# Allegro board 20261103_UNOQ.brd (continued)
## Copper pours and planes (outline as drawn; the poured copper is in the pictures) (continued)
PWR_3P3V on V5: 14.3,7.82 15.24,7.82 15.96,8.54 15.96,11.29 18.24,13.57 20.97,13.57 21.64,12.9 21.64,11.38 22.76,10.26 31.96,10.26 32.58,10.88 32.58,11.64 32.42,11.8 25.18,11.8 21.46,15.52 17.57,15.52 14.51,18.58 14.51,20.65 14.37,20.79 12.71,20.79 12.71,17.95 15.51,15.15 15.51,13.48 14.17,12.14 14.17,7.95
PWR_3P3V on S6: 12.8,30.23 13.34,30.23 13.51,30.05 13.51,27.89 13.26,27.64 12.83,27.64 12.67,27.79 12.67,30.1
PWR_3P3V on G7: 6.48,59.02 6.48,50 7.19,49.29 7.19,47.44 6.81,47.05 6.81,46.14 7.19,45.76 7.19,38.32 4.63,35.76 4.63,32.75 4.06,32.18 1.08,32.18 0.9,32.36 0.9,41.33 4.18,44.61 4.18,60.44 5.6,61.86 9.83,61.86 10.13,61.56 10.13,59.97 9.95,59.79 7.25,59.79
PWR_3P8V on BOTTOM (solid shape): 10.11,46.2 10.11,42.7 9.17,42.7 8.69,42.21 6.88,42.21 6.76,42.34 6.76,43.54 7.75,44.53 7.75,46.18 7.95,46.38 9.93,46.38
PWR_3P8V on V5: 15.47,42.6 15.67,42.39 15.67,42.15 14.72,41.2 13.94,41.2 13.51,40.77 13.51,37.01 13.21,36.7 12.29,36.7 11.86,37.13 11.86,38.2 11.87,38.21 11.87,41.54 11.87,41.54 11.87,42.31 12.16,42.6
PWR_3P8V on S6: 15.63,42.59 15.22,42.59 14.64,42.01 11.42,42.01 10.33,43.1 10.33,43.32 10.14,43.51 9.86,43.51 9.78,43.43 9.78,42.85 11.18,41.45 14.75,41.45 15.67,42.37 15.67,42.55
PWR_3P8V on S6: 10.86,35.15 9.52,33.8 9.52,31.7 9.57,31.64 9.96,31.64 13.01,34.68 13.01,36.28 13.47,36.76 13.47,37.14 13.47,37.14 13.47,37.71 13.38,37.8 11.8,37.8 10.86,36.85
USB_IN_MID on TOP: 40.97,11.76 40.97,12.21 40.65,12.53 40.65,13.13 40.75,13.23 40.87,13.23 41.7,12.4 41.7,11.73 41,11.73
USB_VBUS_IN on TOP: 39.9,9.93 39.9,12.9 40.15,13.15 40.36,13.15 40.55,12.96 40.55,12.53 40.34,12.32 40.34,10.74 40.56,10.52 40.56,9.88 40.54,9.86 39.98,9.86
VCOIN on BOTTOM (solid shape): 8.61,8.94 8.61,7.04 8.38,6.81 6.48,6.81 6.32,6.96 6.32,8.61 6.76,9.04 8.51,9.04
VCONN_IN on TOP (solid shape): 32.31,50.95 32.41,50.85 32.82,50.85 32.87,50.8 32.87,50.39 32.94,50.32 33.38,50.32 33.43,50.27 33.43,50.01 31.72,50.01 31.7,50.04 31.7,51.44 32.31,51.44
VPH_PWR on TOP: 34.81,18.34 34.29,18.34 32.92,19.71 32.36,19.71 32.36,19.15 32.38,19.13 32.87,19.13 33.87,18.13 34.88,18.13 34.88,18.28
VPH_PWR on TOP: 46.56,10.85 46.56,13.84 46.41,14 45.74,14 44.78,14.96 41.92,14.96 41.64,14.68 41.43,14.68 40.89,15.22 40.72,15.22 40.59,15.09 40.59,15.01 41.27,14.33 41.51,14.33 41.78,14.06 43.93,14.06 44.65,13.34 44.65,10.87 44.83,10.69 46.41,10.69
VPH_PWR on S3: 45.82,14.02 45.82,11.61 46.51,11.61 46.51,14.02
VPH_PWR on S6: 46.48,13.94 46.48,11.63 45.77,11.63 45.77,13.94
VPH_PWR on G7: 32.18,17.07 32.18,19.05 32.69,19.56 36.81,19.56 37.8,20.55 39.65,20.55 41.27,18.93 41.27,15.23 40.8,14.76 40.8,13.79 41.08,13.51 45.19,13.51 45.72,14.05 46.15,14.05 46.87,13.33 46.87,11.89 46.32,11.34 37.94,11.34 37.76,11.52 37.76,13.7 38.31,14.25 39.01,14.25 39.22,14.46 39.22,15.44 38.68,15.98 38.68,18.21 38.33,18.57 36.8,18.57 36.27,18.03 36.27,17.37 36.78,16.87 36.78,15.72 36.55,15.49 36.55,15.14 35.84,15.14 35.71,15.27 35.71,16.05 35.31,16.46 32.79,16.46
VREG_L1A_0P848V on TOP: 36.34,17.93 36.34,18.61 35.94,19.01 36.03,19.01 36.03,19.01 35.3,19.01 34.87,19.44 34.87,21.56 35.48,21.56 35.48,19.99 35.93,19.54 36.21,19.54 36.88,18.87 36.88,17.86 36.85,17.83 36.43,17.83
VREG_L1A_0P848V on BOTTOM: 28.21,37.21 28.21,35.45 28.4,35.26 28.4,34.37 28.91,34.37 28.91,35.26 28.72,35.45 28.72,37.27 28.95,37.5 28.95,37.75 28.9,37.8 28.55,37.8 28.5,37.75 28.5,37.49
VREG_L1A_0P848V on BOTTOM: 30.98,35.8 31.3,35.8 31.3,35.42 31.27,35.38 31.17,35.38 31.14,35.35 31.14,32.78 31.65,32.78 31.68,32.81 31.68,33.09 31.65,33.13 31.49,33.13 31.46,33.16 31.46,34.24 31.52,34.3 31.87,34.3 31.9,34.34 31.9,34.62 31.82,34.7 31.6,34.7 31.55,34.75 31.55,36.1 31.3,36.35 31.3,36.75 31.25,36.8 30.96,36.8 30.92,36.75 30.92,35.86
VREG_L1A_0P848V on BOTTOM: 32.44,35.7 32.44,35.35 32.49,35.31 32.49,34.19 32.54,34.14 32.54,33.09 32.44,33 32.44,31.65 32.75,31.65 32.75,31.8 32.82,31.87 32.82,32.59 32.89,32.65 33.21,32.65 33.21,32.94 33.17,32.97 32.97,32.97 32.79,33.15 32.79,34.21 32.73,34.27 32.67,34.27 32.63,34.3 32.63,34.65 32.67,34.69 32.89,34.69 33,34.8 33,36.5 32.7,36.5 32.7,35.96
VREG_L1A_0P848V on G2: 31.2,36.56 31.2,32.65 31.17,32.62 30.18,32.62 29.8,33 29.71,33 29.64,32.94 29.64,32.81 30.22,32.24 31.49,32.24 31.55,32.3 31.55,36.53 31.46,36.62 31.27,36.62
VREG_L1A_0P848V on G2: 28.4,36.91 28.4,35.29 28.31,35.19 27.99,35.19 27.9,35.1 27.77,35.1 27.67,35 27.67,34.43 27.74,34.37 28.21,34.37 28.28,34.43 28.28,34.53 28.21,34.59 28.05,34.59 27.99,34.65 27.99,34.97 28.05,35.03 28.4,35.03 28.44,35 28.44,34.81 28.47,34.78 28.69,34.78 28.75,34.84 28.75,36.91 28.66,37.01 28.5,37.01
VREG_L1A_0P848V on S3: 30.69,32.17 31.39,32.17 31.55,32.33 31.55,36.62 31.49,36.69 31.23,36.69 31.17,36.62 31.17,32.71 31.08,32.62 30.57,32.62 30.47,32.52 30.47,32.4
VREG_L1A_0P848V on S3: 32.38,31.66 32.38,36.94 32.44,37.01 32.67,37.01 32.73,36.94 32.73,31.66 32.67,31.6 32.44,31.6
VREG_L1A_0P848V on S3: 27.67,34.43 27.67,34.62 27.77,34.72 28.18,34.72 28.37,34.91 28.37,36.91 28.44,36.97 28.72,36.97 28.79,36.91 28.79,34.62 28.56,34.4 27.7,34.4
VREG_L1A_0P848V on S6: 32.38,36.59 32.38,34.7 32.78,34.7 32.89,34.81 32.89,36.72 32.51,36.72
VREG_L1A_0P848V on S6: 31.55,36.21 31.55,34.72 31.65,34.62 31.81,34.62 31.87,34.56 31.87,34.43 31.81,34.37 31.58,34.37 31.52,34.3 31.52,33.25 31.71,33.06 31.71,32.94 31.15,32.94 31.15,34.63 31.2,34.69 31.2,35.7 30.98,35.93 30.98,36.47 31.17,36.66 31.46,36.66 31.46,36.31
VREG_L1A_0P848V on S6: 28.91,37.17 28.91,34.43 28.28,34.43 28.28,37.17
VREG_L1A_0P848V on S6: 29.62,30.83 29.72,30.93 29.72,31.46 29.63,31.55 29.35,31.55 29.18,31.72 28.98,31.72 28.85,31.85 28.56,31.85 28.47,31.76 28.47,31.6 28.79,31.28 29.12,31.28 29.24,31.17 29.24,30.91 29.32,30.83
VREG_L1A_0P848V on G7: 34.8,23.6 33.5,24.9 28.7,24.9 26.56,27.04 26.56,32.55 28.34,34.34 28.34,35.07 28.2,35.21 28.2,37.05 28.3,37.15 28.65,37.15 28.79,37.01 32.41,37.01 32.95,36.47 32.95,34.94 32.67,34.65 32.67,33.41 33.21,32.87 33.21,32.01 32.79,31.6 32.28,31.6 32.06,31.82 31.62,31.82 31.35,32.09 29.93,32.09 29.87,32.02 29.87,30.72 29.47,30.32 29.47,28.83 30.15,28.15 35.8,28.15 37.6,26.35 37.6,21.7 35.92,20.02 35.23,20.02 34.8,20.45
VREG_L2A_1P128V on S3: 41.64,42.71 48.32,42.71 48.49,42.55 48.49,26.27 47.28,25.06 44.67,25.06 43.65,24.04 43.22,24.04 42.9,23.72 42.9,22.53 39.47,19.1 39.47,18.36 39.33,18.22 38.22,18.22 38.12,18.32 38.12,18.44 38.73,19.05 38.73,19.65 39.3,20.22 39.3,21.31 40.79,22.81 40.79,24.23 41.33,24.77 41.33,24.78 43.6,27.05 43.6,27.5 43.7,27.59 43.95,27.59 44.32,27.22 46.36,27.22 46.94,27.81 46.94,31.67 46.85,31.77 46.2,31.77 46.13,31.83 46.13,32.21 46.2,32.28 46.83,32.28 46.94,32.39 46.94,33.09 46.24,33.09 46.18,33.16 46.18,35.38 46.31,35.51 46.75,35.51 46.91,35.67 46.91,36.28 46.85,36.35 46.2,36.35 46.13,36.41 46.13,36.82 46.26,36.95 46.83,36.95 46.91,37.03 46.91,41.46 46.69,41.68 44.37,41.68 44.24,41.55 44.24,41.05 44.15,40.95 43.73,40.95 43.64,41.05 43.64,41.52 43.48,41.68 40.42,41.68 40.11,41.36 40.11,41.05 40.04,40.98 39.6,40.98 39.57,41.01 39.57,42.47 39.81,42.71 41.64,42.71
VREG_L2A_1P128V on V5: 40.08,31.88 40.08,30.71 40.26,30.53 40.94,30.53 41.1,30.68 41.1,31.83 40.94,31.98 40.18,31.98
VREG_L2A_1P128V on V5: 42.24,31.88 42.24,30.68 42.39,30.53 42.93,30.53 43.08,30.68 43.08,31.8 42.88,32 42.37,32
VREG_L2A_1P128V on S6: 33.27,31.07 33.27,31.8 33.36,31.9 33.49,31.9 33.56,31.96 33.65,31.96 33.78,32.09 33.78,32.77 33.17,33.38 33.17,33.57 33.35,33.75 33.79,33.75 34.1,34.06 34.1,34.85 33.91,35.04 33.01,35.04 32.95,35.1 32.95,35.4 33.05,35.5 33.5,35.5 33.56,35.56 33.56,36.44 33.49,36.51 33.27,36.51 33.17,36.6 33.17,36.89 33.27,36.98 34.38,36.98 34.99,37.59 38.66,37.59 38.86,37.39 38.86,36.73 38.96,36.63 40.57,36.63 40.63,36.7 40.63,37.37 40.28,37.71 40.28,38.13 40.47,38.32 43.3,38.32 43.46,38.16 43.46,37.14 43.65,36.95 46.39,36.95 46.71,36.63 46.71,31.83 46.46,31.58 39.61,31.58 39.23,31.2 36.43,31.2 36.12,30.88 33.46,30.88
VREG_L2A_1P128V on S6: 39.52,27.69 39.52,26.57 39.65,26.44 43.99,26.44 44.09,26.54 44.09,27.56 44.02,27.64 43.38,27.64 43.33,27.58 43.33,27.05 43.21,26.92 40.36,26.92 40.28,27 40.28,27.66 40.18,27.76 39.6,27.76
VREG_L3A_0P6V on G2: 32.86,37.04 32.86,36.04 33.15,35.75 33.15,35.6 32.86,35.31 32.86,34.81 33.11,34.56 33.11,34.46 32.86,34.21 32.86,33.19 33.08,32.97 33.08,32.81 32.82,32.55 32.82,31.63 32.89,31.57 33.11,31.57 33.21,31.66 33.21,32.46 33.46,32.71 33.46,32.94 33.14,33.25 33.14,33.7 33.36,33.92 33.36,34.69 33.17,34.88 33.17,35.35 33.46,35.64 33.46,35.73 33.17,36.02 33.17,37.04
VREG_L3A_0P6V on S3: 40.69,29.61 43.02,29.61 43.16,29.47 43.16,29.14 42.86,28.84 42.86,28.49 43.19,28.16 43.19,28.02 42.92,27.75 42.92,26.71 41.49,25.28 39.3,25.28 39.17,25.15 39.17,21.8 37.81,20.44 37.81,18.07 37.58,17.84 37.17,17.84 37.17,18.98 36.76,19.39 36.76,22.1 37.55,22.89 37.55,26.65 37.77,26.87 40.76,26.87 40.92,27.03 40.92,27.55 40.55,27.92 40.55,28.36 40.56,28.36 40.92,28.72 40.92,28.87 40.58,29.21 40.58,29.5
VREG_L3A_0P6V on S3: 40.54,38.99 43.08,38.99 43.21,39.12 43.21,39.4 43.08,39.52 42.83,39.52 42.62,39.73 42.62,40.18 42.72,40.28 43.29,40.28 43.45,40.44 43.45,40.7 43.32,40.82 42.87,40.82 42.78,40.92 42.78,40.92 42.43,41.27 41.16,41.27 40.52,40.63 40.52,40.38 40.62,40.28 41,40.28 41.15,40.13 41.15,39.73 40.94,39.52 40.36,39.52 40.3,39.45 40.3,39.23
VREG_L3A_0P6V on V5: 36.07,41.27 47.33,41.27 47.33,27.63 36.63,27.63 35.97,28.29 35.97,34.89 35.53,35.33 35.53,35.42 33.08,35.42 32.7,35.8 32.7,37.2 32.95,37.45 33.3,37.45 33.52,37.67 33.52,38.72
VREG_L3A_0P6V on G7: 32.98,34.53 32.98,37.1 33.24,37.36 33.65,37.36 33.75,37.26 33.75,34.59 33.56,34.4 33.4,34.4 33.3,34.3 33.3,33.79 33.3,33.75 32.95,33.75 32.95,34.49
VREG_L5A_1P232V on V5: 27.32,36.02 27.32,36.75 26.97,37.1 25.45,37.1 22.71,34.37 22.71,18.46 26.52,14.66 31.22,14.66 31.22,13.91 32.44,13.93 32.69,14.17 32.69,14.71 32.54,14.86 31.95,14.86 31.29,15.52 26.96,15.52 23.48,19.01 23.48,34.08 25.38,35.99 27.29,35.99
VREG_L5A_1P232V on S6: 30.53,31.66 30.31,31.44 30.31,28.13 31.17,27.28 31.17,14.48 31.69,13.95 33.22,13.95 33.22,27.03 30.82,29.43 30.82,31.5 30.66,31.66
VREG_L5A_1P232V on G7: 27,36.05 26.27,36.05 26.27,36.75 26.08,36.94 26.08,38.09 26.72,38.72 33.97,38.72 35.25,37.44 35.25,34.8 35.4,34.65 35.4,33.95 35.34,33.89 35.06,33.89 34.83,33.67 34.29,33.67 34.13,33.51 34.13,33.41 34.38,33.16 34.38,31.06 34.19,30.87 30.88,30.87 30.47,31.28 30.47,31.6 30.53,31.66 30.69,31.66 31.01,31.35 33.71,31.35 33.84,31.47 33.84,33.09 33.45,33.49 33.45,34.2 33.5,34.25 34.2,34.25 34.57,34.62 34.57,37.36 33.83,38.1 30.95,38.1 30.71,37.87 30.15,37.87 29.87,37.58 29.26,37.58 28.85,37.99 27.61,37.99 27,37.39
VREG_L7A_0P664V on V5: 31.71,36.4 31.71,36.75 31.9,36.94 31.9,37.2 32.25,37.55 32.25,37.9 31.23,38.91 26.11,38.91 21.81,34.61 21.81,17.97 26.27,13.51 31.29,13.51 31.32,13.49 32.03,13.49 32.84,14.3 32.84,14.78 32.89,14.83 33.38,14.83 34.21,14 34.21,12.62 33.6,12.01 26.08,12.01 21.03,17.07 21.03,34.88 25.64,39.49 31.55,39.49 32.82,38.21 32.82,37.42 32.6,37.2 32.6,36.91 32,36.31 31.81,36.31
VREG_L7A_0P664V on S6: 31.55,36.75 31.55,36.47 31.71,36.31 32.19,36.31 32.35,36.47 32.35,37.61 32.22,37.61 31.97,37.36 31.97,36.88 31.9,36.82 31.62,36.82
VREG_L8A_1P0V on V5: 28.5,33.7 27.83,33.7 27.29,34.24 27.29,34.49 27.16,34.62 27,34.62 26.59,34.21 25.19,34.21 24.68,33.7 24.68,19.93 25.98,18.63 30.64,18.63 32.46,16.81 32.46,16.15 31.72,16.15 30.08,17.9 25.53,17.9 24.05,19.39 24.05,33.95 25.03,34.94 26.69,34.94 26.91,35.16 27.26,35.16 28.34,34.08 28.44,34.08 28.59,33.92 28.59,33.79
VREG_L9A_1P0V on V5: 27.64,33.54 27.64,33.76 27.48,33.92 26.34,33.92 24.84,32.43 24.84,20.18 26.27,18.75 30.68,18.75 32.54,16.89 32.54,15.9 32.66,15.77 33.1,15.77 33.22,15.9 33.22,17.48 31.34,19.36 26.75,19.36 25.45,20.66 25.45,32.18 26.75,33.48 27.58,33.48
VREG_L10A_1P3V on V5: 32.06,37.52 31.65,37.52 30.88,38.28 26.43,38.28 22.55,34.4 22.55,18.4 26.55,14.4 30.4,14.4 30.53,14.53 30.53,14.61 31.14,14.61 31.14,13.87 30.94,13.67 26.31,13.67 21.95,18.02 21.95,34.59 26.15,38.79 31.14,38.79 32.16,37.77 32.16,37.61
VREG_L12A_0P9V on S6: 31.25,30.35 31.25,29.75 33.45,27.55 33.45,13.97 32.79,13.31 32.79,13.03 32.85,12.97 33.84,12.97 34.42,13.55 34.42,24.9 34.6,25.08 34.6,26.2 34.42,26.38 34.42,27.84 32.41,29.85 32.41,31.19 32.32,31.28 32.12,31.28 31.87,31.03 31.87,30.97
VREG_L13A_1P8V on BOTTOM: 31.52,31.05 31.52,29.35 31.4,29.23 31.4,27.35 31.1,27.05 21.31,27.05 21.25,26.99 21.25,26.56 21.31,26.5 31.35,26.5 32,27.15 32,29.2 31.95,29.25 31.95,31.05
VREG_L13A_1P8V on BOTTOM: 25.54,34.88 25.54,34.56 26.02,34.56 26.02,35.89 26.11,35.99 26.53,35.99 26.53,36.31 26.11,36.31 26.02,36.4 26.02,36.97 25.57,36.97 25.57,34.91
VREG_L13A_1P8V on G2: 29.95,34.69 29.95,33.7 29.69,33.44 28.98,33.44 28.88,33.54 28.88,34.65 28.79,34.75 28.44,34.75 28.4,34.78 28.4,34.94 28.37,34.97 28.12,34.97 28.05,34.91 28.05,34.65 28.09,34.62 28.25,34.62 28.28,34.59 28.63,34.59 28.69,34.53 28.69,33.95 28.6,33.86 28.6,33.45 28.69,33.36 28.69,33.29 28.88,33.1 29.78,33.1 30.1,32.78 30.23,32.78 30.3,32.85 30.3,32.95 30.05,33.2 30.05,33.35 30.41,33.71 30.41,34.69
VREG_L13A_1P8V on G2: 29.17,30.33 29.17,30.62 29.59,31.05 31.05,31.05 31.52,30.58 31.52,30.36 31.46,30.3 31.3,30.3 31.05,30.55 29.73,30.55 29.48,30.3 29.2,30.3
VREG_L13A_1P8V on S3: 26.43,36.59 26.43,35.13 26.37,35.07 25.86,35.07 25.73,35.19 25.73,35.38 25.83,35.48 26.15,35.48 26.27,35.61 26.27,35.83 26.02,36.08 26.02,36.56 26.05,36.59
VREG_L13A_1P8V on S6: 25.97,36.92 22.32,36.92 20.85,35.46 20.85,14.34 26.89,8.31 37.54,8.31 37.94,8.71 37.94,9.41 37.75,9.6 35.86,9.6 35.55,9.91 26.91,9.91 21.87,14.95 21.87,33.55 22.95,34.63 25.85,34.63 26.13,34.92 26.13,35.81 26.58,36.25 26.58,36.38 26.48,36.47 26.2,36.47 26.13,36.54 26.13,36.76
VREG_L13A_1P8V on G7: 24.91,34.14 27.04,34.14 27.58,34.69 28.15,34.69 28.21,34.75 28.21,35.1 27.9,35.41 27.9,37.1 28.16,37.36 28.59,37.36 28.7,37.25 31.5,37.25 31.7,37.45 31.7,37.65 31.5,37.85 31.05,37.85 30.72,37.52 29.2,37.52 28.88,37.83 27.55,37.83 27.1,37.39 27.1,35.19 26.97,35.07 26.21,35.07 26.15,35.13 26.15,36.72 25.92,36.94 25.67,36.94 24.91,36.18
VREG_L15A_1P8V on TOP (solid shape): 46.34,60.18 46.34,59.56 45.94,59.16 45.94,57.77 46.41,57.3 46.41,55.98 46.71,55.68 48.16,55.68 48.26,55.58 48.26,54.74 48.13,54.61 45.14,54.61 45.04,54.71 45.04,55.81 45.12,55.89 45.12,57.38 45.04,57.46 45.04,60.11 45.2,60.27 46.25,60.27
VREG_L15A_1P8V on BOTTOM (solid shape): 10.16,8.94 10.16,4.88 10.48,4.56 13.25,4.56 13.48,4.33 13.48,3.77 13.27,3.56 9.86,3.56 8.88,4.54 8.88,8.88 9.01,9.01 10.09,9.01
VREG_L15A_1P8V on BOTTOM (solid shape): 20.07,14.68 20.07,13.26 20.01,13.2 17.98,13.2 17.98,13.87 18.08,13.97 19.28,13.97 19.46,14.15 19.46,14.63 19.56,14.73 20.02,14.73
VREG_L15A_1P8V on S3 (solid shape): 7.45,58.12 7.45,57.12 7.24,56.92 6.43,56.92 6.29,57.06 6.29,58.21 6.31,58.23 7.34,58.23
VREG_L15A_1P8V on S3 (solid shape): 20.75,12.96 20.75,12.33 20.62,12.2 19.72,12.2 19.46,12.46 19.46,13.1 19.56,13.2 20.51,13.2
VREG_L15A_1P8V on S6 (solid shape): 14.57,4.05 14.57,3.61 14.48,3.52 12.73,3.52 12.59,3.66 12.59,4.01 12.76,4.18 14.44,4.18
VREG_L15A_1P8V on S6 (solid shape): 20.65,12.9 20.65,12.42 20.55,12.32 20.02,12.32 18.69,13.64 18.69,13.79 18.85,13.94 19.61,13.94
VREG_L15A_1P8V on BOTTOM: 25.35,32.87 24.61,32.87 24.48,32.75 24.48,31.23 24.54,31.16 25.53,31.16 25.62,31.26 26.51,31.26 26.51,30.66 26.42,30.56 25.11,30.56 24.92,30.37 24.92,28.33 25.11,28.14 29.25,28.14 29.38,28.27 29.38,29.92 29.44,29.99 29.73,29.99 29.82,29.89 29.82,27.44 29.73,27.35 21.09,27.35 20.93,27.19 20.93,25.3 21.68,24.55 21.68,16 21.05,15.37 21.05,14.41 20.85,14.21 20.85,13.4 20.64,13.19 18.69,13.19 18.6,13.28 18.6,13.88 19.88,15.16 19.88,15.77 20.41,16.3 20.41,23.34 19.31,24.44 19.31,29.27 19.91,29.88 19.91,33.88 19.05,34.75 16.65,34.75 16.46,34.56 16.46,33.36 16.37,33.27 15.82,33.27 15.59,33.5 14.97,33.5 14.92,33.55 14.92,34.45 14.16,35.21 14.16,37.24 14.35,37.43 16.59,37.43 16.63,37.39 16.63,37.09 16.23,37.09 15.96,36.82 15.96,36.09 16.1,35.95 21.28,35.95 21.72,36.39 21.72,37.47 22.4,38.15 27.83,38.15 27.9,38.09 27.9,37.74 27.74,37.58 24.97,37.58 24.87,37.48 24.87,33.79 24.97,33.7 25.38,33.7 25.38,32.9
VREG_L15A_1P8V on G2: 26.43,33.76 26.43,33.48 26.37,33.41 26.2,33.41 26.14,33.35 26.14,33.21 26.4,32.95 26.65,32.95 26.8,33.1 26.8,33.7 26.4,34.1 25.59,34.1 25.26,33.76 25.26,33.64 25.3,33.6 25.45,33.6 25.48,33.63 25.48,33.73 25.57,33.83 26.37,33.83
VREG_L15A_1P8V on S3: 13.48,3.38 19.67,3.38 20.11,3.82 20.11,5.89 20.41,6.2 20.41,7.12 20.38,7.16 19.14,7.16 19.01,7.03 19.01,4.49 18.88,4.36 13.51,4.36 13.38,4.23 13.38,3.48
VREG_L15A_1P8V on V4: 20.9,12.22 20.95,12.26 20.95,13.74 20.1,14.59 17.54,14.59 16.78,15.35 16.78,32.26 16.41,32.63 15.18,32.63 11.84,35.97 11.84,38.24 10.76,39.33 10.76,44.2 8.71,46.25 8.71,48.65 7.62,49.74 7.62,51.5 6.18,52.94 6.18,55.97 7.62,57.41 7.62,57.96 7.14,58.44 4.89,58.44 4.45,58 4.45,50.9 5.68,49.67 5.68,39.81 6.04,39.45 7.61,39.45 8.25,38.81 8.25,36.27 10.45,34.07 10.45,30.86 10.75,30.56 13.26,30.56 13.93,29.89 13.93,14.46 16.17,12.22
VREG_L15A_1P8V on V5: 20.32,13.39 19.35,13.39 19.1,13.13 19.1,6.94 19.3,6.74 20.33,6.74 20.68,7.09 20.68,13.03
VREG_L15A_1P8V on V5: 23.26,62.65 23.75,63.15 23.75,65.44 24.75,66.43 27.19,66.43 29.36,64.26 29.36,62.95 29.44,62.86 32.58,62.86 33.34,63.62 42.45,63.62 44.84,61.23 44.84,58.54 45.33,58.05 46.48,58.05 46.75,58.32 46.75,61.43 43.19,64.99 31.02,64.99 28.13,67.88 23.99,67.88 22.55,66.44 22.55,64.28 22.12,63.86 6.28,63.86 5.51,63.09 5.51,57.68 5.82,57.37 7.16,57.37 7.35,57.56 7.35,58.06 6.95,58.47 6.95,61.62 7.98,62.65
VREG_L15A_1P8V on S6: outline of 84 points within 27.48,20.14 47.8,60.3
VREG_L15A_1P8V on S6: 28.27,12.58 29.67,11.18 36.65,11.18 36.65,12.67 31.53,12.67 30.6,13.6 30.6,14.07 30.61,14.08 30.61,26.84 29.91,27.54 29.91,30.06 29.77,30.2 29.37,30.2 29.28,30.11 29.28,29.1 28.39,28.2
VREG_L15A_1P8V on G7: 29.5,29.65 29.5,30.25 30.06,30.81 33.4,30.81 33.4,30.11 33.11,30.11 32.89,30.33 32.62,30.33 32.37,30.08 30.21,30.08 29.78,29.65
VREG_L20A_2P96V on S3: 37.75,11.1 37.75,10.75 37.95,10.55 37.95,9.35 37.6,9 28.95,9 28.3,9.65 28.3,11.15 28.2,11.25 27.55,11.25 27.35,11.05 27.35,9.65 28.45,8.55 37.9,8.55 38.3,8.95 38.3,11.05 38.5,11.25 38.5,14.15 38.4,14.25 38.1,14.25 38.05,14.2 38.05,11.4
VREG_L20A_2P96V on S6: 28.3,11.3 27.75,11.85 27.75,20.8 27.65,20.9 27.2,20.9 27.1,20.8 27.1,11.5 27.85,10.75 28,10.75 28.3,11.05
VREG_L22A_3P3V on TOP (solid shape): 23.65,53.59 23.6,53.54 22.1,53.54 21.62,53.06 21.08,53.06 20.95,53.19 20.95,54.61 21.03,54.69 21.77,54.69 22.1,55.02 23.65,55.02
VREG_L22A_3P3V on S3 (solid shape): 24.3,54.55 24.3,53.45 24.16,53.31 23.37,53.31 22.61,54.08 22.61,54.84 22.68,54.91 23.93,54.91
VREG_L22A_3P3V on V4 (solid shape): 23.67,56.9 23.67,54.42 24.2,53.9 24.2,53.42 24.08,53.3 23.3,53.3 22.76,53.85 22.76,56.82 22.91,56.97 23.6,56.97
VREG_S1A_0P8V on TOP: 39.01,23.47 39.01,21.74 40.74,21.74 40.74,23.47
VREG_S1A_0P8V on BOTTOM: 27.2,31.98 27.2,29.93 27.19,29.94 26.75,29.94 26.7,29.89 26.7,28.62 26.77,28.56 28.07,28.56 28.17,28.65 28.17,29.48 28.07,29.57 28.07,30.13 28.12,30.17 28.12,30.58 28.18,30.65 29.1,30.65 29.17,30.71 29.17,31 29.07,31.09 28.28,31.09 28.18,31.19 28.18,32.01 28.44,32.27 28.44,33.25 28.4,33.29 28.12,33.29 28.09,33.32 28.09,33.64 28.05,33.67 27.61,33.67 27.61,32.4
VREG_S1A_0P8V on G2: 27.16,30.03 27.16,32.19 27.23,32.25 27.54,32.25 27.61,32.31 27.61,33.28 27.7,33.38 28.25,33.38 28.37,33.26 28.37,32 28.31,31.93 28.05,31.93 27.99,31.87 27.99,30.6 27.93,30.54 27.73,30.54 27.54,30.34 27.54,30.03 27.48,29.96 27.23,29.96
VREG_S1A_0P8V on S3: 39.01,23.46 39.01,22.54 40.47,22.54 40.76,22.83 40.76,23.37 40.67,23.46
VREG_S1A_0P8V on S3: 27.16,30.04 27.16,32.24 27.23,32.3 27.51,32.3 27.58,32.36 27.58,33.35 27.67,33.44 28.25,33.44 28.31,33.38 28.31,31.95 28.28,31.92 27.99,31.92 27.93,31.85 27.93,30.46 27.42,29.95 27.26,29.95
VREG_S1A_0P8V on V5: 29.89,21.15 25.8,25.24 25.8,31.35 27.2,32.75 27.2,33.16 27.55,33.51 28.02,33.51 28.21,33.32 28.21,33.09 28.56,32.75 29.55,32.75 30.34,31.95 30.34,26.86 32.66,24.55 35.48,24.55 35.67,24.36 35.67,23.1 35.89,22.89 38.49,22.89 39.65,24.04 41.17,24.04 41.27,23.95 41.27,21.5 40.92,21.15
VREG_S1A_0P8V on S6: 26.89,28.87 26.89,29.38 27.07,29.56 27.07,32.08 27.58,32.59 27.58,33.44 27.77,33.64 27.99,33.64 28.4,33.22 28.4,32.68 28.34,32.62 28.34,32.04 28.09,31.8 28.09,31.36 27.96,31.22 27.96,30.3 27.67,30.01 27.67,29.56 27.98,29.26 27.98,28.91 27.91,28.84 26.93,28.84
VREG_S2A_0P8V on TOP: 35.71,23.47 35.71,21.72 37.42,21.72 37.42,23.47
VREG_S2A_0P8V on BOTTOM: 29.74,33.32 29.74,33.6 29.49,33.86 29.49,35.32 29.33,35.48 29.33,36.82 29.36,36.85 30.76,36.85 30.82,36.78 30.82,36.47 30.79,36.43 29.9,36.43 29.77,36.31 29.77,35.42 29.93,35.26 29.93,33.95 30.15,33.73 30.15,33.35 30.09,33.29 29.77,33.29
VREG_S2A_0P8V on G2: 29.52,33.68 29.52,36.25 29.51,36.25 29.26,36.25 29.2,36.31 29.2,36.63 29.26,36.7 29.51,36.7 29.58,36.76 29.58,37.01 29.64,37.08 31.86,37.08 31.93,37.01 31.93,33.25 31.87,33.19 31.65,33.19 31.58,33.25 31.58,36.56 31.46,36.69 30.95,36.69 30.78,36.52 30.78,33.73 30.7,33.65 30.5,33.65 30.47,33.68 30.47,36.53 30.34,36.66 30.05,36.66 29.87,36.48 29.87,33.72 29.75,33.6 29.6,33.6
VREG_S2A_0P8V on S3: 35.89,23.72 35.89,22.83 37.42,22.83 37.42,23.72
VREG_S2A_0P8V on S3: 29.26,32.84 29.26,33.38 29.51,33.63 29.51,36.19 29.45,36.25 29.32,36.25 29.26,36.31 29.26,36.63 29.32,36.7 29.51,36.7 29.58,36.76 29.58,37.08 29.64,37.14 30.72,37.14 30.78,37.08 30.78,33.69 30.66,33.57 30.5,33.57 30.34,33.74 30.34,36.57 30.27,36.63 30.02,36.63 29.96,36.57 29.96,34.75 29.9,34.69 29.9,34.33 29.96,34.27 29.96,33.57 29.55,33.16 29.55,32.86 29.47,32.78 29.33,32.78
VREG_S2A_0P8V on S3: 31.58,33.57 31.58,36.12 31.65,36.18 31.9,36.18 31.97,36.12 31.97,33.6 31.9,33.54 31.62,33.54
VREG_S2A_0P8V on V5: 30.98,26.47 30.98,31.6 30.92,31.66 30.92,32.17 30.28,32.81 29.77,32.81 28.18,34.4 28.09,34.4 27.35,35.13 27.35,36.75 27.51,36.91 31.58,36.91 33.17,35.32 35.4,35.32 35.89,34.83 35.89,32.6 35.91,32.59 35.91,28.03 37.36,26.58 37.36,23.21 37.16,23.01 35.97,23.01 35.83,23.15 35.83,24.36 35.51,24.68 32.78,24.68
VREG_S2A_0P8V on S6: 27.34,37 27.3,37.04 27.3,37.4 27.4,37.5 27.4,38.9 27.35,38.95 27.1,38.95 27.05,38.9 27.05,36.9 27.39,36.56 27.39,35.66 27.55,35.5 27.55,35.32 27.39,35.16 27.39,34.81 27.93,34.81 27.93,37
VREG_S2A_0P8V on S6: 29.96,36.27 29.96,33.51 29.84,33.38 29.8,33.38 29.55,33.13 29.29,33.13 29.26,33.16 29.26,33.35 29.39,33.48 29.39,36.72 29.55,36.88 30.57,36.88 30.82,36.62 30.82,33.95 30.66,33.79 30.41,33.79 30.41,35.99 30.57,36.15 30.57,36.21 30.38,36.4 30.09,36.4
VREG_S3A_1P352V on TOP: 31,21.74 31.83,21.74 31.93,21.64 31.93,19.99 31.9,19.95 31.29,19.95 31.24,19.9 29.07,19.9 29,19.96 29,21.39 30.66,21.39
VREG_S3A_1P352V on S3: 29.07,21.34 29.07,19.97 30.28,19.97 30.28,21.34
VREG_S3A_1P352V on V5: 28.8,21.03 28.8,20.73 30.06,19.47 32.91,19.47 34.34,18.03 34.34,15.49 34.67,15.16 35.26,15.16 35.38,15.29 35.38,15.54 35.2,15.72 35.15,15.72 35.13,15.75 35.13,16.33 36.07,17.27 38.05,17.27 38.15,17.37 38.15,18.16 38.76,18.77 38.76,19.35 38.63,19.48 37.7,19.48 37.54,19.32 37.54,18.26 37.41,18.14 35.97,18.14 33.6,20.5 31.52,20.5 30.68,21.34 29.11,21.34
VREG_S4A_2P04V on TOP: 31.22,18.39 31.22,16.69 30.3,16.69 29.94,16.33 28.33,16.33 28.27,16.39 28.27,17.79 29.8,17.79 30.4,18.39
VREG_S4A_2P04V on S3: 28.28,17.76 28.28,16.33 29.49,16.33 29.49,17.76
VREG_S4A_2P04V on V5: 41.83,21.2 42.39,21.21 42.55,21.2 42.55,17.64 41.1,16.2 41.1,15.34 39.37,13.61 34.7,13.61 33.4,14.91 32.05,14.91 31.52,15.44 31.52,15.49 31.14,15.88 28.09,15.88 28.04,15.93 28.04,17.83 28.07,17.86 30.02,17.86 31.78,16.1 32.44,16.1 32.49,16.05 32.49,15.9 32.64,15.75 33.1,15.75 33.22,15.88 33.91,15.88 34.67,15.11 34.95,15.11 34.98,15.14 38.33,15.14 40.54,17.35 40.55,17.34 41.68,18.48 41.68,21.06
VSW_CHG on TOP: 40.84,13.77 40.97,13.89 41.07,13.89 41.44,13.53 42.99,13.53 43.13,13.67 43.51,13.67 43.61,13.56 43.61,10.77 42.47,10.77 41.84,11.4 41.84,12.45 40.84,13.45
VSW_S1 on TOP: 40.67,20.16 40.67,20.83 39.01,20.83 39.01,19.76 38.88,19.63 38.88,18.7 38.57,18.38 38.57,18.16 38.6,18.13 38.88,18.13 39.14,18.38 39.14,18.98 39.22,19.06 39.57,19.06
VSW_S2 on TOP: 37.1,18.53 37.1,18.4 37.45,18.05 37.55,18.05 37.71,18.21 37.71,18.37 37.42,18.66 37.42,18.95 37.55,19.08 37.55,19.65 37.42,19.78 37.42,20.8 35.76,20.8 35.76,19.96 36.03,19.69 36.4,19.69 37.17,18.92 37.17,18.6
VSW_S3 on TOP: 32.82,21.69 32.82,19.96 34.04,18.75 34.04,18.72 34.35,18.4 34.53,18.4 34.62,18.5 34.62,19.1 33.68,20.04 33.68,21.69
VSW_S4 on TOP: 33.83,17.53 32.97,18.39 32.11,18.39 32.11,16.69 32.99,16.69 33.35,17.04 33.78,17.04 34.04,17.3 34.37,17.3 34.67,16.99 34.77,16.99 34.85,17.07 34.85,17.19 34.51,17.53

Small or netless copper shapes (teardrops, artwork), in the pictures only: 18 on TOP, 20 on BOTTOM, 21 on S3, 1 on V4, 28 on S6, 2 on G7, 10 on G2

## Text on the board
Ref Des/Silkscreen Bottom: 2025/11/27 | 48DMVQ101.0GAJV
User.7: Wi-Fi Dual Band | Printed ANTENNA
User.40: 4.00 | 5.00 | 10.00 | 53.34 | 40.00 | 108.68 | 3.00 | 15.00 | n | 0.8 | 8.00 | 1.50 | 68.58 | 6.00 | 159.16 | 2.50 | ` | 0.05
User.45: FIGURE | FINISHED_SIZE | 0.1 | 0.2032 | 1.05 | 1.21 | 0.5 | 0.8 | 3.2 | 1.2x0.7 | 1.7x0.6 | 2.1x0.6 | 0.2 | ROTATION | - | 0.000 | 90.000 | DRILL CHART: TOP to G2 | ALL UNITS ARE IN MILLIMETERS | DRILL CHART: G2 to S3 | TOLERANCE_DRILL | +0.0/-0.1 | DRILL CHART: TOP to BOTTOM | DRILL CHART: S3 to S6 | DRILL CHART: G7 to BOTTOM | DRILL CHART: S6 to G7 | +0.0762/-0.0762 | +0.0508/-0.0508 | TOLERANCE_TRAVEL | PLATED | NON-PLATED | QTY | 2856 | 2360 | 221 | 32 | 6 | 2 | 4 | 850 | 2099 | 1428
